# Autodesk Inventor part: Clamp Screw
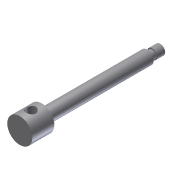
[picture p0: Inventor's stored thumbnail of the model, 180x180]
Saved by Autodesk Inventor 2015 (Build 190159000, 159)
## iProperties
Shininess: 77.0
Length Units: 11269
Angle Units: 11279
Time Units: 11290
Mass Units: 11283
Length Display Precision: 3
Angle Display Precision: 2
Created: 2002-02
Part Number: Clamp Screw
Document SubType Name: Modeling
Designer: ***
Density: 1 g/cm^3
Material: Generic
Appearance: Default
Density: 0.0
Volumn: 0.0
Area: 0.0
PropertySet Name: Model Information
Control State: 0
Master: False
Checked Out: False
Author: ***
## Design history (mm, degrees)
sketch "Sketch1"
  geometry: L1 (0, 140)-(5, 140); L2 (5, 140)-(5, 132); L3 (5, 132)-(4, 132); L4 (4, 132)-(4, 127); L5 (4, 127)-(6.5, 127); L6 (6.5, 127)-(6.5, 25); L7 (6.5, 25)-(4, 25); L8 (4, 25)-(4, 22); L9 (4, 22)-(12.5, 22); L10 (12.5, 22)-(12.5, 0); L11 (12.5, 0)-(0, 0); L12 (0, 0)-(0, 140)
  constraints: 24 end point, 10 parallel, 1 horizontal, 1 perpendicular
  dimensions: "d0" = 10 diameter of L2 L12; "d1" = 8 diameter of L4 L12; "d2" = 13 diameter of L6 L12; "d3" = 8 diameter of L7.end L12; "d4" = 25 diameter of L10 L12; "d5" = 3 distance from line of L7.end L9; "d6" = 8 distance of L1.end L2.end; "d7" = 13 vertical distance of L1.end L5.end; "d8" = 22 distance of L9.end L10.end; "d10" = 102 distance of L5.end L6.end
revolve "Revolution1" sketch "Sketch1" stored, may be unused: angle "d11" = 90 deg
sketch "Sketch3"
  geometry: L1 (-12.5, 0)-(12.5, 0) reference; C1 r 5 at (-0.113, 11)
  constraints: 1 centre point
  dimensions: "d13" = 10 diameter of C1; "d14" = 11 distance from line of L1 C1.centre
extrude "Extrusion1" cut sketch "Sketch3" stored distance "d15" = 10; taper "d16" = 0 deg
body "Solid1"
